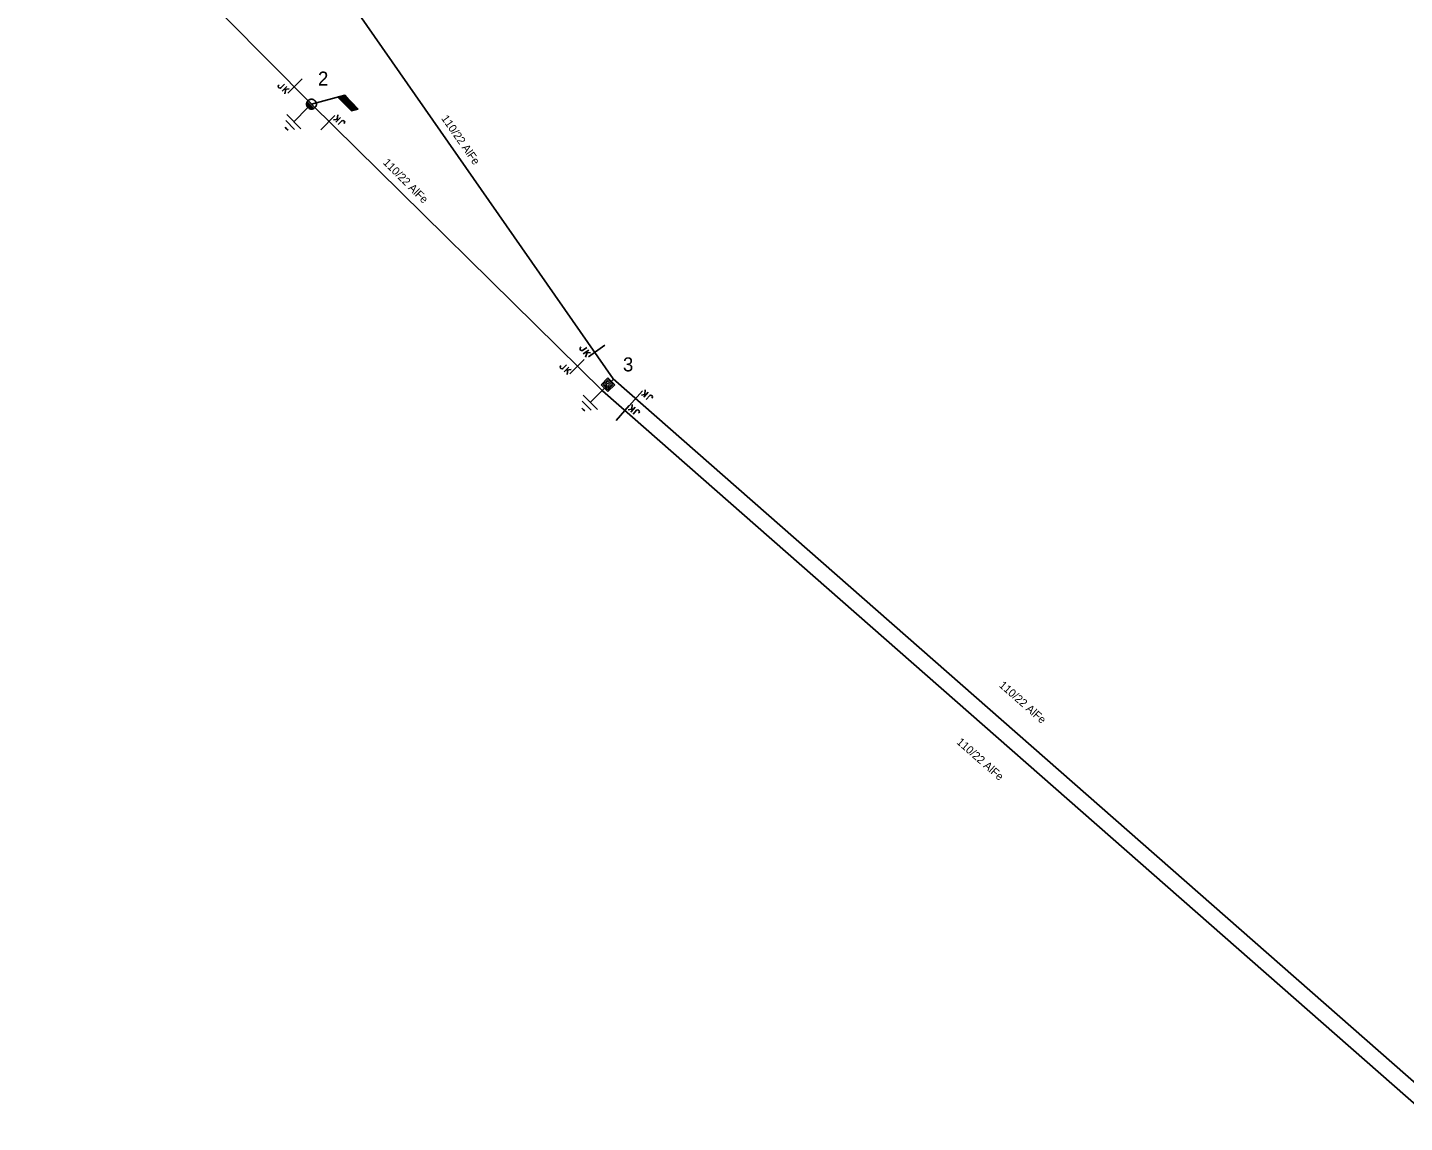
# Model space of a CAD drawing. Extents: x -545588 to -543214, y -1196037 to -1194452.
# Drawn here: x -545161.1 to -544989.1, y -1195057.3 to -1194920.5 of the extents above; entities that cross this region are included whole.
import ezdxf

# ---------------------------------------------------------------- set-up
doc = ezdxf.new("R2010")
doc.units = 0
for name, color, linetype in [('DOPLŇ_POPISY', 7, 'Continuous'), ('ELE_EON', 7, 'Continuous'), ('ELE_EON_POPIS', 7, 'Continuous'), ('Implicitní', 7, 'Continuous'), ('POL_ZNAČKA_PRACOVNÍ', 7, 'Continuous'), ('TECH_OCHR_PÁSMO_HRAN', 7, 'Continuous'), ('Vrstva 18', 7, 'Continuous')]:
    doc.layers.add(name, color=color, linetype=linetype)

# ---------------------------------------------------------------- blocks, each defined once
blk = doc.blocks.new('VN840')
at = {"layer": 'POL_ZNAČKA_PRACOVNÍ'}
for points in [[(-0.01, 1.41), (-0.01, -1.09)], [(-1.51, -1.24), (-1.51, -1.15)], [(-1.48, -1.35), (-1.51, -1.24)], [(-1.33, -1.42), (-1.48, -1.35)], [(-1.27, -1.42), (-1.33, -1.42)], [(-1.13, -1.35), (-1.27, -1.42)], [(-1.09, -1.24), (-1.13, -1.35)], [(-1.09, -0.59), (-1.09, -1.24)], [(-0.68, -0.59), (-0.68, -1.42)], [(-0.68, -1.11), (-0.27, -0.59)], [(-0.54, -0.94), (-0.2, -1.42)]]:
    blk.add_lwpolyline(points, dxfattribs=at)
blk = doc.blocks.new('VN810')
at = {"layer": 'POL_ZNAČKA_PRACOVNÍ'}
for points in [[(0, -1.25), (0, -3.75)], [(1.25, -3.75), (-1.25, -3.75)], [(0.77, -4.37), (-0.8, -4.37)], [(0, -5), (-0.25, -5)], [(0.27, -5), (0, -5)]]:
    blk.add_lwpolyline(points, dxfattribs=at)
blk = doc.blocks.new('VN001')
at = {"layer": 'Implicitní'}
for p, q in [((1.99, 3.48), (4.4, 3.48)), ((2.02, 3.53), (4.43, 3.53)), ((2.05, 3.58), (4.46, 3.58)), ((2.07, 3.63), (4.49, 3.63)), ((2.1, 3.68), (4.52, 3.68)), ((2.13, 3.73), (2.54, 3.73)), ((1.73, 3.03), (4.14, 3.03)), ((1.76, 3.08), (4.17, 3.08)), ((1.79, 3.13), (4.2, 3.13)), ((1.82, 3.18), (4.23, 3.18)), ((1.85, 3.23), (4.26, 3.23)), ((1.87, 3.28), (4.29, 3.28)), ((1.9, 3.33), (4.32, 3.33)), ((1.93, 3.38), (4.35, 3.38)), ((1.96, 3.43), (4.37, 3.43))]:
    blk.add_line(p, q, dxfattribs=at)
blk.add_lwpolyline([(2.13, 3.73), (0, 0)], dxfattribs=at)
blk.add_lwpolyline([(4.55, 3.73), (2.13, 3.73), (1.7, 2.98), (4.12, 2.99)], close=True, dxfattribs=at)
blk = doc.blocks.new('VN440')
at = {"layer": 'ELE_EON_POPIS'}
for points in [[(1.22, 0), (1.21, 0.13), (1.19, 0.25), (1.16, 0.38), (1.11, 0.5), (1.05, 0.61), (0.98, 0.72), (0.9, 0.82), (0.81, 0.91), (0.71, 0.99), (0.6, 1.06), (0.49, 1.12), (0.37, 1.16), (0.25, 1.2), (0.12, 1.22), (-0.01, 1.22), (-0.14, 1.22), (-0.26, 1.2), (-0.39, 1.16), (-0.51, 1.12), (-0.62, 1.06), (-0.73, 0.99), (-0.83, 0.91), (-0.92, 0.82), (-1, 0.72), (-1.07, 0.61), (-1.13, 0.5), (-1.18, 0.38), (-1.21, 0.25), (-1.23, 0.13), (-1.24, 0), (-1.23, -0.13), (-1.21, -0.26), (-1.18, -0.38), (-1.13, -0.5), (-1.07, -0.62), (-1, -0.73), (-0.92, -0.83), (-0.83, -0.92), (-0.73, -1), (-0.62, -1.07), (-0.51, -1.13), (-0.39, -1.17), (-0.26, -1.2), (-0.14, -1.23), (-0.01, -1.23), (0.12, -1.23), (0.25, -1.2), (0.37, -1.17), (0.49, -1.13), (0.6, -1.07), (0.71, -1), (0.81, -0.92), (0.9, -0.83), (0.98, -0.73), (1.05, -0.62), (1.11, -0.5), (1.16, -0.38), (1.19, -0.26), (1.21, -0.13), (1.22, 0)], [(-1.24, 0), (1.22, 0)], [(-1.18, -0.34), (1.1, -0.34)], [(-1.01, -0.63), (0.97, -0.63)], [(-0.74, -0.92), (0.68, -0.92)]]:
    blk.add_lwpolyline(points, dxfattribs=at)
blk = doc.blocks.new('VN470')
at = {"layer": 'ELE_EON_POPIS'}
for points in [[(-1.23, 1.22), (1.23, 1.22)], [(-1.23, -1.23), (-1.23, 1.22)], [(-0.92, 0.9), (0.92, 0.9)], [(-0.92, -0.95), (-0.92, 0.9)], [(-0.61, 0.61), (0.61, 0.61)], [(-0.61, -0.62), (-0.61, 0.61)], [(-0.31, -0.27), (-0.31, 0.34)], [(-0.31, 0.34), (0.31, 0.34)], [(0, 1.22), (0, 1.97)], [(0.31, 0.34), (0.31, -0.27)], [(0.61, 0.61), (0.61, -0.62)], [(0.92, 0.9), (0.92, -0.95)], [(1.23, 1.22), (1.23, -1.23)], [(1.23, -1.23), (-1.23, -1.23)], [(0.92, -0.95), (-0.92, -0.95)], [(0.61, -0.62), (-0.61, -0.62)], [(0.31, -0.27), (-0.31, -0.27)], [(0, -1.23), (0, -1.98)]]:
    blk.add_lwpolyline(points, dxfattribs=at)

msp = doc.modelspace()

# ---------------------------------------------------------------- linework, layer by layer
at = {"layer": 'ELE_EON'}
for points in [[(-545145.32, -1194882.87), (-545144.58, -1194883.9), (-545122.84, -1194914.32), (-545087.92, -1194964.41)], [(-545125.62, -1194930.11), (-545157.44, -1194897.99), (-545161.09, -1194894.1)], [(-545089.24, -1194965.91), (-545125.62, -1194930.11)]]:
    msp.add_lwpolyline(points, dxfattribs=at)
at = {"layer": 'Implicitní'}
for points in [[(-545087.92, -1194964.41), (-544969.06, -1195068.81), (-544833.21, -1195149.88), (-544688.64, -1195235.58), (-544556.54, -1195314.1), (-544420.62, -1195395.04), (-544280.05, -1195478.05), (-544140.98, -1195560.03), (-544005.82, -1195639.79), (-543873.77, -1195718.4), (-543750.46, -1195791.32), (-543648.45, -1195852.42)], [(-545089.24, -1194965.91), (-544970.24, -1195070.43), (-544834.23, -1195151.6), (-544689.66, -1195237.3), (-544557.56, -1195315.82), (-544421.64, -1195396.76), (-544281.07, -1195479.77), (-544142, -1195561.75), (-544006.84, -1195641.51), (-543874.79, -1195720.12), (-543751.48, -1195793.04), (-543649.47, -1195854.14)]]:
    msp.add_lwpolyline(points, dxfattribs=at)

# ---------------------------------------------------------------- block references
at = {"layer": 'DOPLŇ_POPISY'}
for name, p, xscale, yscale, rotation in [('VN440', (-545125.61, -1194930.11), 0.5, 0.5, -45.2964556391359), ('VN470', (-545088.58, -1194965.16), 0.4999999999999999, 0.5000000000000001, 135.01100502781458)]:
    msp.add_blockref(name, p, dxfattribs=dict(at, xscale=xscale, yscale=yscale, rotation=rotation))
at = {"layer": 'POL_ZNAČKA_PRACOVNÍ'}
for p, rotation in [((-545125.17, -1194929.66), -45.29695556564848), ((-545088.13, -1194964.71), -44.98899498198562)]:
    msp.add_blockref('VN810', p, dxfattribs=dict(at, rotation=rotation))
at = {"layer": 'TECH_OCHR_PÁSMO_HRAN', "rotation": -45.29673610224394}
msp.add_blockref('VN001', (-545125.62, -1194930.11), dxfattribs=at)
at = {"layer": 'Vrstva 18'}
for p, rotation in [((-545127.79, -1194927.96), -45.29645278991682), ((-545123.47, -1194932.29), 135.1667500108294), ((-545090.11, -1194961.05), -55.01524725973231), ((-545092.55, -1194963.03), -44.83325003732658), ((-545085, -1194966.72), 138.67199996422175), ((-545086.64, -1194968.57), 138.68738612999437)]:
    msp.add_blockref('VN840', p, dxfattribs=dict(at, rotation=rotation))

# ---------------------------------------------------------------- texts
at = {"layer": 'ELE_EON_POPIS'}
for rotation, p in [(304.985, (-545109.45, -1194931.89)), (315.167, (-545116.75, -1194937.5)), (318.672, (-545039.8, -1195002.82)), (318.687, (-545045.1, -1195009.93))]:
    msp.add_text('110/22 AlFe', height=1, rotation=rotation, dxfattribs=at).set_placement(p)
at = {"layer": 'POL_ZNAČKA_PRACOVNÍ'}
for s, p in [('2', (-545124.81, -1194927.79)), ('3', (-545086.71, -1194963.5))]:
    msp.add_text(s, height=1.75, dxfattribs=at).set_placement(p)

doc.saveas('drawing.dxf')
